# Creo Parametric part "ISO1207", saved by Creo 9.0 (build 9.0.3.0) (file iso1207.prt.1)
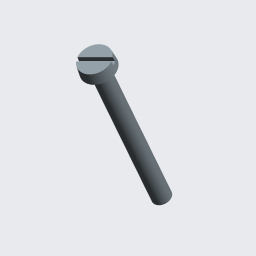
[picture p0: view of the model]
Units: millimeter Kilogram Sec (mmKs); MM, KILOGRAM, SECS

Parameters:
  PLACEMENT = "A"
  BENENNUNG = "Zylinderschraube"
  NORMINFO = "Zylinderschrauben mit Schlitz; Produktklasse A"
  BEZEICHNUNG = "ISO 1207 - M d x l"
  MATERIAL = "Stahl 4.8"

Other parameters: MAJOR_DIAMETER, THREADS_PER_INCH, METRIC, KATEGORIE, GEWICHT

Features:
  1. datum plane "PL1"
  2. datum plane "PL2"
  3. datum plane "PL3"
  4. datum axis
  5. protrusion
  6. cut
  7. round

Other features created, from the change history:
  component interface "Komponentenschnittstelle ID 870"
  component interface "Komponentenschnittstelle ID 871"

Other named items: PL4

Named dimensions: Gewindedurchmesser, Kopfdurchmesser, Laenge, Kopfhoehe, Gewindelaenge, Kerndurchmesser, Werkzeugfuegebreite, Werkzeugfuegetiefe, Radius

Layers: DETAILS, GEWINDE, PLAZIERUNG

Family table entries: EI1207M1_6X2V4, ISO1207, value(d_val), value(s_val), ISO 1207 - M 1.6 X 2 - Stahl 4.8, 3Stahl 4.8, value(i_val), EI1207M1_6X3V4, ISO1207, )ISO 1207 - M 1.6 X 3 - Stahl 4.8, 3Stahl 4.8, EI1207M1_6X4V4, ISO1207, )ISO 1207 - M 1.6 X 4 - Stahl 4.8, 3Stahl 4.8, EI1207M1_6X5V4, ISO1207, )ISO 1207 - M 1.6 X 5 - Stahl 4.8, 3Stahl 4.8, EI1207M1_6X6V4, ISO1207, )ISO 1207 - M 1.6 X 6 - Stahl 4.8, 3Stahl 4.8, EI1207M1_6X8V4, ISO1207, 2/ , )ISO 1207 - M 1.6 X 8 - Stahl 4.8, 3Stahl 4.8, EI1207M1_6X10V4, ISO1207, 2/$, )ISO 1207 - M 1.6 X 10 - Stahl 4.8, 3Stahl 4.8, EI1207M1_6X12V4, ISO1207, 2/(, )ISO 1207 - M 1.6 X 12 - Stahl 4.8, 3Stahl 4.8, EI1207M1_6X14V4, ISO1207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

Surfaces: 7 plane, 3 cylinder, 2 cone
